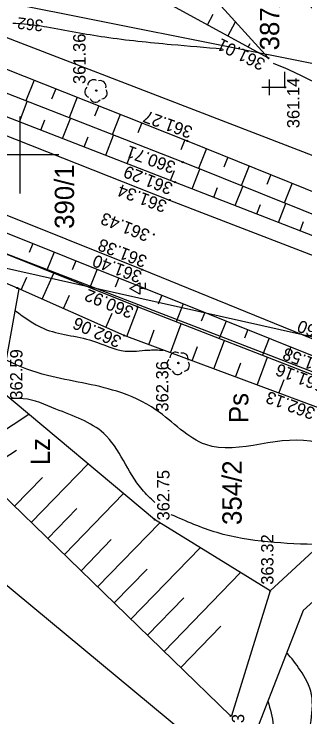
# Model space of a CAD drawing. Extents: x 4635329 to 4651863, y 5356628 to 5367582.
# Drawn here: x 4651136.61 to 4651155.45, y 5356669.94 to 5356715.48 of the extents above; entities that cross this region are included whole.
import ezdxf

# ---------------------------------------------------------------- set-up
doc = ezdxf.new("R2010")
doc.units = 0
for name, color, linetype in [('Level 1', 7, 'Continuous'), ('Level 12', 7, 'Continuous'), ('Level 20', 7, 'Continuous'), ('Level 24', 7, 'Continuous'), ('Level 4', 7, 'Continuous'), ('Level 44', 7, 'Continuous'), ('Level 45', 7, 'Continuous'), ('Level 46', 7, 'Continuous'), ('Level 47', 7, 'Continuous'), ('Level 48', 7, 'Continuous'), ('Level 5', 7, 'Continuous'), ('Level 54', 7, 'Continuous'), ('Level 55', 7, 'Continuous'), ('Level 60', 7, 'Continuous')]:
    doc.layers.add(name, color=color, linetype=linetype)

msp = doc.modelspace()

# ---------------------------------------------------------------- linework, layer by layer
at = {"layer": 'Level 1'}
msp.add_line((4651116.718, 5356694.556), (4651150.17, 5356666.828), dxfattribs=at)
at = {"layer": 'Level 20'}
for points in [[(4651122.765, 5356712.887), (4651146.685, 5356703.427), (4651159.565, 5356698.457), (4651170.205, 5356694.067), (4651178.895, 5356691.327), (4651182.663, 5356690.554), (4651185.995, 5356690.057), (4651193.465, 5356690.007), (4651201.855, 5356691.047)], [(4651201.455, 5356686.167), (4651194.035, 5356685.457), (4651185.485, 5356685.017), (4651181.21, 5356685.664), (4651178.315, 5356686.247), (4651168.145, 5356689.587), (4651157.765, 5356693.687), (4651144.895, 5356698.917), (4651120.155, 5356708.837)], [(4651164.505, 5356690.097), (4651163.815, 5356687.907), (4651153.195, 5356678.107)], [(4651167.725, 5356688.857), (4651166.435, 5356686.877), (4651155.343, 5356676.839)], [(4651153.195, 5356678.107), (4651150.695, 5356670.007)], [(4651155.343, 5356676.839), (4651152.438, 5356669.398)]]:
    msp.add_lwpolyline(points, dxfattribs=at)
at = {"layer": 'Level 24'}
for p, q in [((4651145.105, 5356698.072), (4651145.105, 5356697.697)), ((4651145.105, 5356697.697), (4651144.755, 5356697.697))]:
    msp.add_line(p, q, dxfattribs=at)
msp.add_lwpolyline([(4651144.755, 5356698.072), (4651144.755, 5356697.322), (4651144.105, 5356697.697)], close=True, dxfattribs=at)
at = {"layer": 'Level 4'}
for p, q in [((4651159.614, 5356704.887), (4651123.689, 5356718.747)), ((4651130.975, 5356717.257), (4651177.535, 5356707.977)), ((4651169.904, 5356686.914), (4651125.563, 5356703.993)), ((4651174.835, 5356690.307), (4651125.405, 5356701.397))]:
    msp.add_line(p, q, dxfattribs=at)
at = {"layer": 'Level 44'}
for centre in [(4651153.085, 5356712.617), (4651141.935, 5356710.517), (4651154.155, 5356710.727), (4651147.825, 5356707.257), (4651147.535, 5356705.877), (4651147.035, 5356704.587), (4651146.685, 5356703.427), (4651145.665, 5356701.197), (4651144.895, 5356698.917), (4651136.825, 5356697.727), (4651145.105, 5356697.697), (4651144.585, 5356696.527), (4651143.745, 5356694.647), (4651147.255, 5356692.867), (4651145.705, 5356682.727), (4651153.195, 5356678.107), (4651150.635, 5356670.007)]:
    msp.add_circle(centre, 0.04, dxfattribs=at)
at = {"layer": 'Level 46'}
for points in [[(4651163.601, 5356712.367), (4651161.083, 5356712.669), (4651155.2, 5356716.489), (4651152.41, 5356718.49), (4651149.802, 5356719.218), (4651148.043, 5356719.036), (4651147.174, 5356719.006)], [(4651136.534, 5356714.889), (4651137.269, 5356714.845), (4651138.743, 5356714.649)], [(4651138.743, 5356714.649), (4651142.486, 5356713.996), (4651146.792, 5356713.511), (4651150.115, 5356713.224)], [(4651153.387, 5356712.298), (4651154.663, 5356711.755), (4651158.242, 5356710.118), (4651161.638, 5356709.572), (4651164.792, 5356708.905), (4651168.007, 5356706.601), (4651170.554, 5356704.842), (4651175.916, 5356703.398), (4651176.89, 5356703.203)], [(4651136.698, 5356696.252), (4651138.535, 5356695.098), (4651141.689, 5356694.31), (4651143.812, 5356693.643), (4651145.268, 5356693.703), (4651146.277, 5356693.703)], [(4651156.765, 5356687.524), (4651156.246, 5356687.701), (4651149.028, 5356687.58), (4651145.813, 5356689.823), (4651143.266, 5356691.036), (4651138.778, 5356692.066), (4651136.17, 5356693.037), (4651136.124, 5356693.062)], [(4651145.718, 5356683.839), (4651144.904, 5356684.669), (4651142.417, 5356688.307), (4651139.324, 5356689.884), (4651137.201, 5356690.551), (4651136.38, 5356690.551)], [(4651156.433, 5356681.095), (4651149.756, 5356681.88), (4651146.786, 5356683.038)], [(4651155.447, 5356666.303), (4651155.811, 5356669.456), (4651155.871, 5356671.396), (4651155.144, 5356672.972), (4651154.276, 5356674.106)], [(4651153.044, 5356670.951), (4651153.385, 5356669.395), (4651153.203, 5356667.152), (4651153.191, 5356665.214)]]:
    msp.add_spline(points, degree=3, dxfattribs=at)
at = {"layer": 'Level 48'}
for p, q in [((4651149.135, 5356714.773), (4651149.511, 5356715.463)), ((4651150.452, 5356714.054), (4651150.954, 5356714.974)), ((4651151.768, 5356713.336), (4651151.894, 5356713.566)), ((4651137.914, 5356711.196), (4651137.377, 5356709.845)), ((4651139.308, 5356710.642), (4651139.041, 5356709.971)), ((4651140.702, 5356710.088), (4651140.171, 5356708.753)), ((4651136.956, 5356708.504), (4651137.464, 5356709.811)), ((4651142.096, 5356709.534), (4651141.832, 5356708.871)), ((4651139.753, 5356707.417), (4651140.259, 5356708.719)), ((4651143.49, 5356708.98), (4651142.966, 5356707.662)), ((4651138.355, 5356707.96), (4651138.608, 5356708.613)), ((4651144.884, 5356708.426), (4651144.623, 5356707.771)), ((4651141.151, 5356706.874), (4651141.403, 5356707.524)), ((4651142.549, 5356706.33), (4651143.053, 5356707.628)), ((4651147.672, 5356707.318), (4651147.415, 5356706.671)), ((4651143.947, 5356705.787), (4651144.199, 5356706.435)), ((4651149.063, 5356706.758), (4651148.545, 5356705.471)), ((4651150.454, 5356706.197), (4651150.195, 5356705.554)), ((4651151.846, 5356705.636), (4651151.328, 5356704.352)), ((4651146.743, 5356704.7), (4651146.994, 5356705.346)), ((4651148.141, 5356704.157), (4651148.638, 5356705.434)), ((4651153.237, 5356705.076), (4651152.978, 5356704.434)), ((4651149.539, 5356703.613), (4651149.785, 5356704.244)), ((4651150.937, 5356703.069), (4651151.422, 5356704.315)), ((4651154.628, 5356704.515), (4651154.112, 5356703.233)), ((4651153.733, 5356701.982), (4651154.205, 5356703.196)), ((4651152.335, 5356702.526), (4651152.574, 5356703.14)), ((4651155.131, 5356701.438), (4651155.364, 5356702.037)), ((4651137.826, 5356700.614), (4651137.589, 5356700.023)), ((4651139.218, 5356700.056), (4651138.744, 5356698.873)), ((4651140.611, 5356699.498), (4651140.373, 5356698.906)), ((4651138.438, 5356697.009), (4651139.189, 5356698.695)), ((4651142.003, 5356698.94), (4651141.528, 5356697.755)), ((4651137.068, 5356697.619), (4651137.432, 5356698.437)), ((4651143.395, 5356698.382), (4651143.158, 5356697.789)), ((4651139.809, 5356696.399), (4651140.195, 5356697.267)), ((4651146.18, 5356697.265), (4651145.944, 5356696.678)), ((4651143.924, 5356694.58), (4651144.642, 5356696.505)), ((4651147.572, 5356696.707), (4651147.106, 5356695.546)), ((4651142.549, 5356695.179), (4651142.958, 5356696.098)), ((4651148.964, 5356696.148), (4651148.734, 5356695.575)), ((4651150.356, 5356695.589), (4651149.902, 5356694.457)), ((4651145.33, 5356694.056), (4651145.685, 5356695.008)), ((4651146.735, 5356693.532), (4651147.438, 5356695.417)), ((4651151.748, 5356695.03), (4651151.524, 5356694.472)), ((4651149.546, 5356692.484), (4651150.234, 5356694.328)), ((4651153.14, 5356694.471), (4651152.697, 5356693.369)), ((4651148.141, 5356693.008), (4651148.488, 5356693.94)), ((4651154.532, 5356693.912), (4651154.314, 5356693.369)), ((4651152.357, 5356691.436), (4651153.03, 5356693.24)), ((4651150.952, 5356691.96), (4651151.292, 5356692.872)), ((4651153.763, 5356690.912), (4651154.095, 5356691.804)), ((4651133.932, 5356687.153), (4651137.56, 5356689.561)), ((4651134.761, 5356685.904), (4651136.76, 5356687.23)), ((4651137.719, 5356682.544), (4651141.401, 5356686.338)), ((4651136.642, 5356683.588), (4651138.446, 5356685.446)), ((4651139.871, 5356680.454), (4651143.706, 5356684.405)), ((4651138.795, 5356681.499), (4651140.674, 5356683.435)), ((4651142.024, 5356678.365), (4651146.051, 5356682.514)), ((4651140.948, 5356679.409), (4651142.903, 5356681.424)), ((4651144.177, 5356676.275), (4651148.666, 5356680.901)), ((4651143.1, 5356677.32), (4651145.229, 5356679.514)), ((4651146.33, 5356674.186), (4651151.281, 5356679.288)), ((4651145.253, 5356675.231), (4651147.613, 5356677.662)), ((4651147.406, 5356673.141), (4651149.997, 5356675.811))]:
    msp.add_line(p, q, dxfattribs=at)
for points in [[(4651129.435, 5356727.747), (4651147.415, 5356718.887), (4651153.085, 5356712.617)], [(4651153.085, 5356712.617), (4651128.035, 5356726.287)], [(4651123.975, 5356716.737), (4651147.825, 5356707.257), (4651160.975, 5356701.957), (4651171.645, 5356698.197), (4651179.505, 5356694.897)], [(4651179.485, 5356693.387), (4651171.315, 5356696.747), (4651160.495, 5356700.667), (4651147.535, 5356705.877), (4651123.495, 5356715.267)], [(4651122.975, 5356713.937), (4651147.035, 5356704.587), (4651159.995, 5356699.547), (4651170.765, 5356695.237), (4651179.005, 5356692.387)], [(4651119.725, 5356707.867), (4651145.105, 5356697.697), (4651157.435, 5356692.747), (4651164.505, 5356690.097)], [(4651119.395, 5356706.647), (4651144.585, 5356696.527), (4651156.915, 5356691.727), (4651164.127, 5356689.012)], [(4651163.815, 5356687.907), (4651156.325, 5356689.957), (4651143.745, 5356694.647), (4651136.825, 5356697.727), (4651118.775, 5356705.457)], [(4651153.195, 5356678.107), (4651145.705, 5356682.727), (4651135.765, 5356691.067), (4651136.953, 5356697.669)], [(4651150.635, 5356670.007), (4651135.675, 5356684.527), (4651131.275, 5356691.157), (4651131.695, 5356695.267), (4651124.665, 5356696.357), (4651116.943, 5356694.991)]]:
    msp.add_lwpolyline(points, dxfattribs=at)
at = {"layer": 'Level 54'}
for p, q in [((4651154.155, 5356710.727), (4651154.155, 5356711.727)), ((4651153.155, 5356710.227), (4651153.155, 5356711.227)), ((4651154.155, 5356710.727), (4651152.655, 5356710.727))]:
    msp.add_line(p, q, dxfattribs=at)
at = {"layer": 'Level 55'}
for centre in [(4651141.935, 5356710.517), (4651147.255, 5356692.867)]:
    msp.add_circle(centre, 0.045, dxfattribs=at)
for centre, start, end in [((4651141.757, 5356710.847), 58.348, 178.132), ((4651142.194, 5356710.788), 346.3906, 106.042), ((4651141.566, 5356710.45), 130.3488, 250.1306), ((4651142.273, 5356710.354), 274.3875, 34.0933), ((4651141.885, 5356710.146), 202.4389, 322.0902), ((4651147.077, 5356693.197), 58.348, 178.132), ((4651147.514, 5356693.138), 346.3906, 106.042), ((4651146.886, 5356692.8), 130.3488, 250.1306), ((4651147.593, 5356692.704), 274.3875, 34.0933), ((4651147.205, 5356692.496), 202.4389, 322.0902)]:
    msp.add_arc(centre, 0.375, start, end, dxfattribs=at)
at = {"layer": 'Level 60'}
for p, q in [((4651137.015, 5356703.847), (4651137.015, 5356708.847)), ((4651139.515, 5356706.347), (4651134.515, 5356706.347))]:
    msp.add_line(p, q, dxfattribs=at)

# ---------------------------------------------------------------- texts
at = {"layer": 'Level 12'}
for s, p in [('Ps', (4651151.779, 5356688.978)), ('Lz', (4651138.935, 5356686.245))]:
    msp.add_text(s, height=1.25, rotation=90, dxfattribs=at).set_placement(p)
at = {"layer": 'Level 45'}
for s, rotation, p in [('361.36', 90, (4651141.24, 5356710.94)), ('361.01', 153.9684, (4651152.958, 5356712.497)), ('361.14', 90, (4651155.093, 5356708.08)), ('361.27', 160.1214, (4651148.24, 5356708.142)), ('360.71', 160.0995, (4651147.139, 5356705.864)), ('361.29', 158.4311, (4651146.96, 5356704.48)), ('361.34', 159.6299, (4651146.577, 5356703.334)), ('361.43', 158.4523, (4651145.476, 5356701.446)), ('361.38', 158.6741, (4651145.294, 5356699.76)), ('361.40', 159.6311, (4651144.955, 5356698.774)), ('360.92', 157.9231, (4651144.429, 5356696.461)), ('362.06', 156.1307, (4651143.643, 5356694.549)), ('361.60', 158.7202, (4651158.201, 5356694.493)), ('362.59', 90, (4651137.159, 5356690.49)), ('361.58', 159.2614, (4651157.26, 5356692.726)), ('362.36', 90, (4651146.606, 5356689.72)), ('361.16', 159.1455, (4651156.809, 5356691.689)), ('362.13', 159.5732, (4651156.181, 5356689.919)), ('362.75', 90, (4651146.676, 5356682.665)), ('363.32', 90, (4651153.408, 5356678.499)), ('365.23', 90, (4651151.515, 5356666.858))]:
    msp.add_text(s, height=0.8, rotation=rotation, dxfattribs=at).set_placement(p)
at = {"layer": 'Level 47'}
msp.add_text('362', height=0.75, rotation=173.4965, dxfattribs=at).set_placement((4651138.535, 5356715.083))
at = {"layer": 'Level 5'}
for s, p in [('387/2', (4651153.783, 5356713.124)), ('390/1', (4651140.497, 5356701.559)), ('354/2', (4651151.351, 5356682.373))]:
    msp.add_text(s, height=1.25, rotation=90, dxfattribs=at).set_placement(p)

doc.saveas('drawing.dxf')
